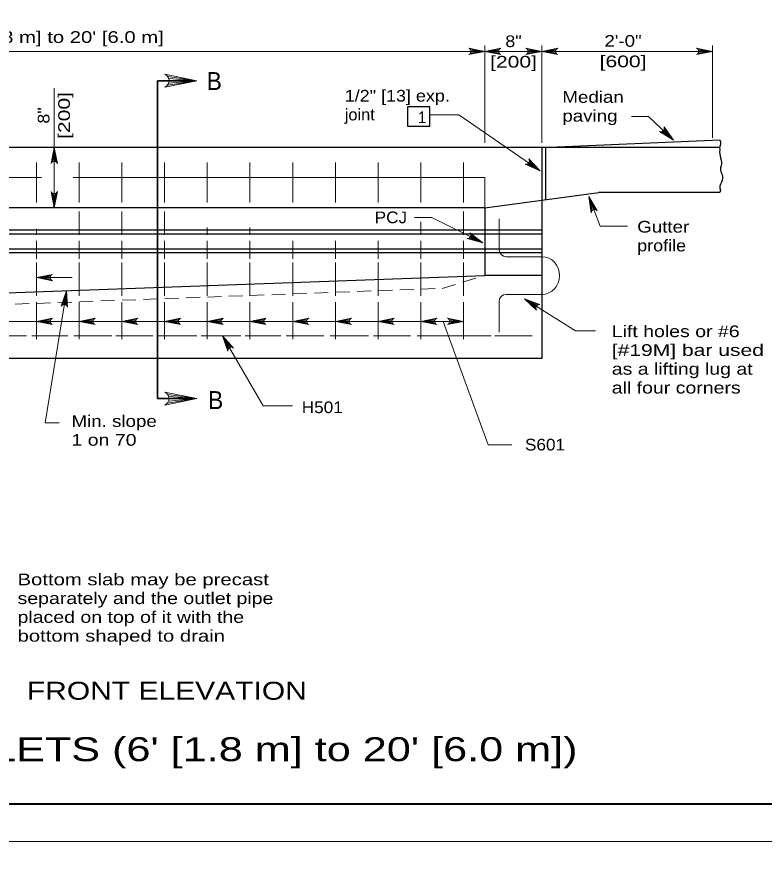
# Model space of a CAD drawing. Extents: x 339.1 to 373.1, y 1412.7 to 1456.7.
# Drawn here: x 351.05 to 361.04, y 1434.5 to 1445.77 of the extents above; entities that cross this region are included whole.
import ezdxf
from ezdxf.enums import TextEntityAlignment as Align

# ---------------------------------------------------------------- set-up
doc = ezdxf.new("R2010")
doc.units = 0
doc.header["$LTSCALE"] = 0.062
doc.linetypes.add('LONG_DASHED', pattern=[7.5, 6, -1.5])
doc.linetypes.add('MEDIUM_DASHED', pattern=[4.5, 3, -1.5])
doc.layers.add('1', color=7, linetype='Continuous', lineweight=13)

msp = doc.modelspace()

# ---------------------------------------------------------------- linework, layer by layer
at = {"layer": '1'}
for p, q in [((357.30708, 1444.08292), (357.30708, 1445.3825)), ((358.06858, 1444.08292), (358.06858, 1445.3825)), ((360.353, 1444.149), (360.353, 1445.3825)), ((357.11092, 1445.27383), (357.30708, 1445.30383)), ((357.11317, 1445.33092), (357.30708, 1445.30383)), ((357.11833, 1445.28642), (357.30708, 1445.30383)), ((357.11975, 1445.3175), (357.30708, 1445.30383)), ((357.12175, 1445.30383), (357.30708, 1445.30383)), ((357.50092, 1445.33092), (357.30708, 1445.30383)), ((357.49442, 1445.3175), (357.30708, 1445.30383)), ((357.94383, 1445.30383), (357.30708, 1445.30383)), ((357.49242, 1445.30383), (357.30708, 1445.30383)), ((357.49583, 1445.28642), (357.30708, 1445.30383)), ((357.50325, 1445.27383), (357.30708, 1445.30383)), ((358.06858, 1445.30383), (357.84117, 1445.30383)), ((357.87233, 1445.27383), (358.06858, 1445.30383)), ((357.87467, 1445.33092), (358.06858, 1445.30383)), ((357.87983, 1445.28642), (358.06858, 1445.30383)), ((357.88125, 1445.3175), (358.06858, 1445.30383)), ((357.88325, 1445.30383), (358.06858, 1445.30383)), ((358.26242, 1445.33092), (358.06858, 1445.30383)), ((358.25592, 1445.3175), (358.06858, 1445.30383)), ((359.55533, 1445.30383), (358.06858, 1445.30383)), ((358.25392, 1445.30383), (358.06858, 1445.30383)), ((358.25733, 1445.28642), (358.06858, 1445.30383)), ((358.26475, 1445.27383), (358.06858, 1445.30383)), ((360.353, 1445.30383), (359.55533, 1445.30383)), ((360.15683, 1445.27383), (360.353, 1445.30383)), ((360.15917, 1445.33092), (360.353, 1445.30383)), ((360.16425, 1445.28642), (360.353, 1445.30383)), ((360.16567, 1445.3175), (360.353, 1445.30383)), ((360.16767, 1445.30383), (360.353, 1445.30383)), ((353.06233, 1444.85225), (353.45467, 1444.91225)), ((353.06683, 1444.9665), (353.45467, 1444.91225)), ((353.07717, 1444.87742), (353.45467, 1444.91225)), ((353.08, 1444.93967), (353.45467, 1444.91225)), ((353.084, 1444.91225), (353.45467, 1444.91225)), ((359.66933, 1444.23083), (359.82817, 1444.11633)), ((359.68333, 1444.23592), (359.82817, 1444.11633)), ((359.69425, 1444.2445), (359.82817, 1444.11633)), ((359.70383, 1444.25942), (359.82817, 1444.11633)), ((359.70717, 1444.27367), (359.82817, 1444.11633)), ((351.51883, 1443.82525), (351.54883, 1444.02142)), ((351.53142, 1443.83267), (351.54883, 1444.02142)), ((351.54883, 1443.83608), (351.54883, 1444.02142)), ((351.56258, 1443.83408), (351.54883, 1444.02142)), ((351.576, 1443.8275), (351.54883, 1444.02142)), ((351.31033, 1443.81992), (351.31033, 1443.28475)), ((351.88142, 1443.81992), (351.88142, 1443.28475)), ((352.4525, 1443.81992), (352.4525, 1443.28475)), ((353.02367, 1443.81992), (353.02367, 1443.28475)), ((353.59475, 1443.81992), (353.59475, 1443.28475)), ((354.16592, 1443.81992), (354.16592, 1443.28475)), ((354.737, 1443.81992), (354.737, 1443.28475)), ((355.30817, 1443.81992), (355.30817, 1443.28475)), ((355.87925, 1443.81992), (355.87925, 1443.28475)), ((356.45042, 1443.81992), (356.45042, 1443.28475)), ((357.0215, 1443.81992), (357.0215, 1443.28475)), ((357.87158, 1443.79808), (358.046, 1443.70917)), ((357.88467, 1443.80533), (358.046, 1443.70917)), ((357.89417, 1443.81542), (358.046, 1443.70917)), ((357.90133, 1443.83167), (358.046, 1443.70917)), ((357.9025, 1443.84617), (358.046, 1443.70917)), ((351.37842, 1443.61833), (345.21833, 1443.61833)), ((357.30708, 1443.61833), (351.80117, 1443.61833)), ((357.30708, 1443.61833), (357.30708, 1443.21525)), ((351.52167, 1443.40908), (351.54883, 1443.21525)), ((351.53517, 1443.40258), (351.54883, 1443.21525)), ((351.57883, 1443.41142), (351.54883, 1443.21525)), ((351.56625, 1443.404), (351.54883, 1443.21525)), ((351.54883, 1443.40058), (351.54883, 1443.21525)), ((358.75925, 1443.18775), (358.69825, 1443.36275)), ((358.74392, 1443.17883), (358.69825, 1443.36275)), ((358.7345, 1443.16767), (358.69825, 1443.36275)), ((358.77283, 1443.19042), (358.69825, 1443.36275)), ((358.78767, 1443.18867), (358.69825, 1443.36275)), ((351.88142, 1443.16433), (351.88142, 1442.85133)), ((352.4525, 1443.16433), (352.4525, 1442.85133)), ((353.02367, 1443.16433), (353.02367, 1442.85133)), ((357.0215, 1443.16433), (357.0215, 1442.85133)), ((356.45042, 1443.02467), (356.45042, 1442.85133)), ((357.49742, 1443.06392), (357.49742, 1442.66083)), ((351.31033, 1442.93283), (351.31033, 1442.85133)), ((353.59475, 1442.95117), (353.59475, 1442.85133)), ((354.16592, 1442.95117), (354.16592, 1442.85133)), ((351.31033, 1442.77108), (351.31033, 1442.53025)), ((351.88142, 1442.77108), (351.88142, 1442.53025)), ((352.4525, 1442.77108), (352.4525, 1442.53025)), ((353.02367, 1442.77108), (353.02367, 1442.53025)), ((353.59475, 1442.77108), (353.59475, 1442.53025)), ((354.16592, 1442.77108), (354.16592, 1442.53025)), ((354.737, 1442.77108), (354.737, 1442.53025)), ((355.30817, 1442.77108), (355.30817, 1442.53025)), ((355.87925, 1442.77108), (355.87925, 1442.53025)), ((356.45042, 1442.77108), (356.45042, 1442.53025)), ((357.0215, 1442.77108), (357.0215, 1442.53025)), ((357.09442, 1442.80792), (357.28025, 1442.74625)), ((357.10625, 1442.81708), (357.28025, 1442.74625)), ((357.11417, 1442.8285), (357.28025, 1442.74625)), ((357.11775, 1442.86017), (357.28025, 1442.74625)), ((357.11875, 1442.84558), (357.28025, 1442.74625)), ((357.12208, 1442.82042), (357.28025, 1442.74625)), ((358.06858, 1442.56008), (357.59258, 1442.56008)), ((351.31033, 1442.48217), (351.31033, 1442.03675)), ((351.88142, 1442.48217), (351.88142, 1442.03675)), ((352.4525, 1442.48217), (352.4525, 1442.03675)), ((353.02367, 1442.48217), (353.02367, 1442.03675)), ((353.59475, 1442.48217), (353.59475, 1442.03675)), ((354.16592, 1442.48217), (354.16592, 1442.03675)), ((354.737, 1442.48217), (354.737, 1442.03675)), ((355.30817, 1442.48217), (355.30817, 1442.03675)), ((355.87925, 1442.48217), (355.87925, 1442.03675)), ((356.45042, 1442.48217), (356.45042, 1442.03675)), ((357.0215, 1442.48217), (357.0215, 1442.03675)), ((351.50417, 1442.30783), (351.31033, 1442.28075)), ((351.49758, 1442.29442), (351.31033, 1442.28075)), ((351.78717, 1442.28075), (351.31033, 1442.28075)), ((351.49558, 1442.28075), (351.31033, 1442.28075)), ((351.49908, 1442.26333), (351.31033, 1442.28075)), ((351.5065, 1442.25075), (351.31033, 1442.28075)), ((351.65492, 1441.91467), (351.7135, 1442.10425)), ((351.66842, 1441.92017), (351.7135, 1442.10425)), ((351.68617, 1441.921), (351.7135, 1442.10425)), ((351.69942, 1441.917), (351.7135, 1442.10425)), ((351.71175, 1441.9085), (351.7135, 1442.10425)), ((358.06858, 1442.05642), (357.59258, 1442.05642)), ((357.99617, 1441.89917), (357.83875, 1441.99708)), ((357.98983, 1441.88258), (357.83875, 1441.99708)), ((357.9895, 1441.868), (357.83875, 1441.99708)), ((358.00508, 1441.90975), (357.83875, 1441.99708)), ((358.01775, 1441.91767), (357.83875, 1441.99708)), ((357.83875, 1441.99708), (358.51858, 1441.56975)), ((351.31033, 1441.95242), (351.31033, 1441.45883)), ((351.88142, 1441.95242), (351.88142, 1441.45883)), ((352.4525, 1441.95242), (352.4525, 1441.45883)), ((353.02367, 1441.95242), (353.02367, 1441.45883)), ((353.59475, 1441.95242), (353.59475, 1441.45883)), ((354.16592, 1441.95242), (354.16592, 1441.45883)), ((354.737, 1441.95242), (354.737, 1441.45883)), ((355.30817, 1441.95242), (355.30817, 1441.45883)), ((355.87925, 1441.95242), (355.87925, 1441.45883)), ((356.45042, 1441.95242), (356.45042, 1441.45883)), ((357.0215, 1441.95242), (357.0215, 1441.45883)), ((357.49742, 1441.95567), (357.49742, 1441.5525)), ((351.50417, 1441.72317), (351.31033, 1441.696)), ((351.49758, 1441.70975), (351.31033, 1441.696)), ((351.49558, 1441.696), (351.31033, 1441.696)), ((351.49908, 1441.67858), (351.31033, 1441.696)), ((351.5065, 1441.66608), (351.31033, 1441.696)), ((352.07533, 1441.72317), (351.88142, 1441.696)), ((352.06875, 1441.70975), (351.88142, 1441.696)), ((352.06675, 1441.696), (351.88142, 1441.696)), ((352.07017, 1441.67858), (351.88142, 1441.696)), ((352.07758, 1441.66608), (351.88142, 1441.696)), ((352.64642, 1441.72317), (352.4525, 1441.696)), ((352.63983, 1441.70975), (352.4525, 1441.696)), ((352.63783, 1441.696), (352.4525, 1441.696)), ((352.64125, 1441.67858), (352.4525, 1441.696)), ((352.64875, 1441.66608), (352.4525, 1441.696)), ((353.21758, 1441.72317), (353.02367, 1441.696)), ((353.211, 1441.70975), (353.02367, 1441.696)), ((353.209, 1441.696), (353.02367, 1441.696)), ((353.21242, 1441.67858), (353.02367, 1441.696)), ((353.21983, 1441.66608), (353.02367, 1441.696)), ((353.78867, 1441.72317), (353.59475, 1441.696)), ((353.78208, 1441.70975), (353.59475, 1441.696)), ((353.78008, 1441.696), (353.59475, 1441.696)), ((353.7835, 1441.67858), (353.59475, 1441.696)), ((353.79092, 1441.66608), (353.59475, 1441.696)), ((354.35975, 1441.72317), (354.16592, 1441.696)), ((354.35325, 1441.70975), (354.16592, 1441.696)), ((354.16592, 1441.696), (354.737, 1441.696)), ((354.35125, 1441.696), (354.16592, 1441.696)), ((354.35467, 1441.67858), (354.16592, 1441.696)), ((354.36208, 1441.66608), (354.16592, 1441.696)), ((354.93092, 1441.72317), (354.737, 1441.696)), ((354.92433, 1441.70975), (354.737, 1441.696)), ((354.92233, 1441.696), (354.737, 1441.696)), ((354.92575, 1441.67858), (354.737, 1441.696)), ((354.93317, 1441.66608), (354.737, 1441.696)), ((355.502, 1441.72317), (355.30817, 1441.696)), ((355.4955, 1441.70975), (355.30817, 1441.696)), ((355.4935, 1441.696), (355.30817, 1441.696)), ((355.49692, 1441.67858), (355.30817, 1441.696)), ((355.50433, 1441.66608), (355.30817, 1441.696)), ((356.07317, 1441.72317), (355.87925, 1441.696)), ((356.06658, 1441.70975), (355.87925, 1441.696)), ((356.06458, 1441.696), (355.87925, 1441.696)), ((356.068, 1441.67858), (355.87925, 1441.696)), ((356.07542, 1441.66608), (355.87925, 1441.696)), ((356.64425, 1441.72317), (356.45042, 1441.696)), ((356.63767, 1441.70975), (356.45042, 1441.696)), ((356.63567, 1441.696), (356.45042, 1441.696)), ((356.63917, 1441.67858), (356.45042, 1441.696)), ((356.64658, 1441.66608), (356.45042, 1441.696)), ((356.82533, 1441.66608), (357.0215, 1441.696)), ((356.82758, 1441.72317), (357.0215, 1441.696)), ((356.83275, 1441.67858), (357.0215, 1441.696)), ((356.83417, 1441.70975), (357.0215, 1441.696)), ((356.83617, 1441.696), (357.0215, 1441.696)), ((358.51858, 1441.56975), (358.78617, 1441.56975)), ((351.17533, 1441.50208), (350.67025, 1441.50208)), ((351.72858, 1441.50208), (351.24758, 1441.50208)), ((352.32033, 1441.50208), (351.81033, 1441.50208)), ((352.86867, 1441.50208), (352.37325, 1441.50208)), ((353.45558, 1441.50208), (352.93608, 1441.50208)), ((354.0425, 1441.50208), (353.51342, 1441.50208)), ((353.89333, 1441.34258), (353.7985, 1441.50183)), ((353.88008, 1441.33075), (353.7985, 1441.50183)), ((353.87308, 1441.31792), (353.7985, 1441.50183)), ((353.90617, 1441.34783), (353.7985, 1441.50183)), ((353.921, 1441.34908), (353.7985, 1441.50183)), ((354.5765, 1441.50208), (354.10025, 1441.50208)), ((355.15383, 1441.50208), (354.64867, 1441.50208)), ((355.75033, 1441.50208), (355.24033, 1441.50208)), ((356.31325, 1441.50208), (355.81767, 1441.50208)), ((357.39083, 1441.50208), (356.39983, 1441.50208)), ((357.93925, 1441.50208), (357.439, 1441.50208)), ((353.06233, 1440.60367), (353.45467, 1440.66358)), ((353.06683, 1440.71783), (353.45467, 1440.66358)), ((353.07717, 1440.62875), (353.45467, 1440.66358)), ((353.08, 1440.691), (353.45467, 1440.66358)), ((353.084, 1440.66358), (353.45467, 1440.66358))]:
    msp.add_line(p, q, dxfattribs=at)
at = {"layer": '1', "lineweight": 35}
for p, q in [((352.93117, 1444.91225), (353.31067, 1444.91225)), ((352.93117, 1440.66358), (353.31067, 1440.66358))]:
    msp.add_line(p, q, dxfattribs=at)
at = {"layer": '1', "lineweight": 25}
for p, q in [((358.06858, 1444.02142), (360.44992, 1444.12217)), ((360.4375, 1444.02142), (345.16325, 1444.02142)), ((358.06858, 1444.02142), (358.06858, 1441.19975)), ((358.11617, 1444.02142), (358.11625, 1443.32233)), ((357.30708, 1443.21525), (358.83033, 1443.41675)), ((360.44992, 1443.41675), (358.83033, 1443.41675)), ((357.30708, 1443.21525), (347.12208, 1443.21525)), ((357.30708, 1443.21525), (357.30708, 1442.30825)), ((358.06858, 1442.91292), (349.66017, 1442.91292)), ((358.06858, 1442.8625), (349.62733, 1442.8625)), ((351.31033, 1442.61058), (345.21833, 1442.61058)), ((358.06858, 1442.61058), (351.29592, 1442.61058)), ((348.97067, 1442.00592), (357.30708, 1442.30825)), ((358.06858, 1442.30825), (357.30708, 1442.30825))]:
    msp.add_line(p, q, dxfattribs=at)
at = {"layer": '1', "linetype": 'LONG_DASHED'}
for points in [[(339.0605, 1434.7455), (373.0605, 1434.7455), (373.0605, 1456.7455), (339.0605, 1456.7455)], [(339.0605, 1412.7455), (373.0605, 1412.7455), (373.0605, 1434.7455), (339.0605, 1434.7455)]]:
    msp.add_lwpolyline(points, close=True, dxfattribs=at)
at = {"layer": '1', "lineweight": 25}
for points in [[(372.5605, 1435.2455), (341.0605, 1435.2455), (341.0605, 1456.2455)], [(360.44992, 1444.12217), (360.45758, 1444.09642), (360.458, 1444.07008), (360.45375, 1444.04483), (360.44658, 1444.0185), (360.44758, 1443.99075), (360.44658, 1443.95792), (360.44942, 1443.93267), (360.45183, 1443.90583), (360.45658, 1443.8795), (360.46575, 1443.85133), (360.471, 1443.8255), (360.4705, 1443.79875), (360.46575, 1443.77242), (360.45992, 1443.74567), (360.45942, 1443.71892), (360.46475, 1443.69258), (360.47717, 1443.66683), (360.48717, 1443.63908), (360.48617, 1443.61075), (360.48192, 1443.58292), (360.471, 1443.55617), (360.458, 1443.52833), (360.45092, 1443.50217), (360.44992, 1443.47683), (360.45658, 1443.45), (360.44992, 1443.41675), (360.45133, 1443.41917)], [(358.06858, 1442.661), (351.29075, 1442.661), (345.21833, 1442.661)], [(358.06858, 1441.19975), (345.50033, 1441.19975), (345.21833, 1441.19975)]]:
    msp.add_lwpolyline(points, dxfattribs=at)
at = {"layer": '1', "lineweight": 40}
msp.add_lwpolyline([(341.0605, 1456.2455), (372.5605, 1456.2455), (372.5605, 1435.2455), (341.0605, 1435.2455)], close=True, dxfattribs=at)
at = {"layer": '1'}
for points in [[(357.30708, 1445.30383), (354.73217, 1445.30383), (345.97983, 1445.30383)], [(357.09292, 1445.261), (357.30708, 1445.30383), (357.09292, 1445.34667)], [(357.52125, 1445.261), (357.30708, 1445.30383), (357.52125, 1445.34667)], [(357.85442, 1445.261), (358.06858, 1445.30383), (357.85442, 1445.34667)], [(358.28275, 1445.261), (358.06858, 1445.30383), (358.28275, 1445.34667)], [(360.13883, 1445.261), (360.353, 1445.30383), (360.13883, 1445.34667)], [(353.02633, 1444.82658), (353.45467, 1444.91225), (353.02633, 1444.99792)], [(351.54883, 1443.21525), (351.54883, 1443.4015), (351.54883, 1444.81458)], [(358.046, 1443.70917), (356.959, 1444.458), (356.5695, 1444.458)], [(359.82817, 1444.11633), (359.49667, 1444.43425), (359.26833, 1444.43425)], [(359.703, 1444.29533), (359.82817, 1444.11633), (359.64383, 1444.2335)], [(351.506, 1443.80725), (351.54883, 1444.02142), (351.59167, 1443.80725)], [(357.89508, 1443.86708), (358.046, 1443.70917), (357.846, 1443.79683)], [(351.59167, 1443.42942), (351.54883, 1443.21525), (351.506, 1443.42942)], [(358.72833, 1443.14642), (358.69825, 1443.36275), (358.80925, 1443.17467)], [(358.69825, 1443.36275), (358.84958, 1442.96658), (359.21292, 1442.96658)], [(357.28025, 1442.74625), (356.59983, 1443.08392), (356.36592, 1443.08392)], [(357.10725, 1442.87967), (357.28025, 1442.74625), (357.06925, 1442.80283)], [(351.5245, 1442.23792), (351.31033, 1442.28075), (351.5245, 1442.32358)], [(351.6395, 1441.89875), (351.7135, 1442.10425), (351.72425, 1441.88617)], [(351.70908, 1442.06767), (351.42625, 1440.33958), (351.61467, 1440.33958)], [(357.998, 1441.84758), (357.83875, 1441.99708), (358.04325, 1441.92033)], [(350.16808, 1441.696), (350.73917, 1441.696), (351.31033, 1441.696), (351.88142, 1441.696), (352.4525, 1441.696), (353.02367, 1441.696), (353.59475, 1441.696), (354.16592, 1441.696)], [(351.5245, 1441.65317), (351.31033, 1441.696), (351.5245, 1441.73883)], [(352.09558, 1441.65317), (351.88142, 1441.696), (352.09558, 1441.73883)], [(352.66667, 1441.65317), (352.4525, 1441.696), (352.66667, 1441.73883)], [(353.23783, 1441.65317), (353.02367, 1441.696), (353.23783, 1441.73883)], [(353.80892, 1441.65317), (353.59475, 1441.696), (353.80892, 1441.73883)], [(354.38008, 1441.65317), (354.16592, 1441.696), (354.38008, 1441.73883)], [(354.95117, 1441.65317), (354.737, 1441.696), (354.95117, 1441.73883)], [(357.0215, 1441.696), (356.45042, 1441.696), (355.87925, 1441.696), (355.30817, 1441.696), (354.737, 1441.696)], [(355.52233, 1441.65317), (355.30817, 1441.696), (355.52233, 1441.73883)], [(356.09342, 1441.65317), (355.87925, 1441.696), (356.09342, 1441.73883)], [(356.66458, 1441.65317), (356.45042, 1441.696), (356.66458, 1441.73883)], [(356.75125, 1441.696), (357.35058, 1440.04542), (357.6665, 1440.04542)], [(356.80733, 1441.65317), (357.0215, 1441.696), (356.80733, 1441.73883)], [(353.87125, 1441.29592), (353.7985, 1441.50183), (353.94492, 1441.33975)], [(353.7985, 1441.50183), (354.34342, 1440.56683), (354.73508, 1440.56683)], [(353.02633, 1440.57792), (353.45467, 1440.66358), (353.02633, 1440.74925)]]:
    msp.add_lwpolyline(points, dxfattribs=at)
at = {"layer": '1', "lineweight": 35}
msp.add_lwpolyline([(352.93117, 1444.91225), (352.93117, 1443.94808), (352.93117, 1440.66358)], dxfattribs=at)
at = {"layer": '1', "lineweight": 25}
msp.add_lwpolyline([(356.27083, 1444.56425), (356.27083, 1444.30267), (356.5695, 1444.30267), (356.5695, 1444.56425)], close=True, dxfattribs=at)
at = {"layer": '1', "linetype": 'MEDIUM_DASHED'}
msp.add_lwpolyline([(349.02583, 1441.85192), (356.73592, 1442.13683), (357.30708, 1442.30825)], dxfattribs=at)
at = {"layer": '1'}
for centre, radius, start, end in [((357.07559, 1445.30385), 0.04623, 292.08605, 67.91218), ((357.53852, 1445.30385), 0.04623, 112.08782, 247.91395), ((357.83708, 1445.30385), 0.04623, 292.08605, 67.91218), ((358.30001, 1445.30385), 0.04623, 112.08782, 247.91395), ((360.12156, 1445.30385), 0.04623, 292.08605, 67.91218), ((352.99173, 1444.91235), 0.09245, 292.08605, 67.91218), ((359.66089, 1444.27634), 0.04623, 248.35541, 24.18154), ((351.54888, 1443.78996), 0.04623, 22.08782, 157.91395), ((357.85635, 1443.84184), 0.04623, 257.09017, 32.9163), ((351.54879, 1443.44669), 0.04623, 202.08782, 337.91395), ((358.77451, 1443.14424), 0.04623, 41.32463, 177.15076), ((357.07276, 1442.84889), 0.04623, 265.74352, 41.56965), ((351.54176, 1442.28078), 0.04623, 112.08782, 247.91395), ((351.67939, 1441.87534), 0.04623, 13.60269, 149.42881), ((358.03534, 1441.87485), 0.04623, 80.20777, 216.0339), ((351.54176, 1441.69609), 0.04623, 112.08782, 247.91395), ((352.11288, 1441.69609), 0.04623, 112.08782, 247.91395), ((352.684, 1441.69609), 0.04623, 112.08782, 247.91395), ((353.25512, 1441.69609), 0.04623, 112.08782, 247.91395), ((353.82624, 1441.69609), 0.04623, 112.08782, 247.91395), ((354.39736, 1441.69609), 0.04623, 112.08782, 247.91395), ((354.96848, 1441.69609), 0.04623, 112.08782, 247.91395), ((355.5396, 1441.69609), 0.04623, 112.08782, 247.91395), ((356.11072, 1441.69609), 0.04623, 112.08782, 247.91395), ((356.68184, 1441.69609), 0.04623, 112.08782, 247.91395), ((356.79003, 1441.69609), 0.04623, 292.08605, 67.91218), ((353.91697, 1441.30296), 0.04623, 52.8601, 188.68622), ((352.99173, 1440.66369), 0.09245, 292.08605, 67.91218)]:
    msp.add_arc(centre, radius, start, end, dxfattribs=at)
for centre, major_axis, start_param, end_param in [((357.59262, 1442.66086), (0, 0.10078), 1.57079628, 3.14159256), ((358.06855, 1442.30825), (0, 0.25194), 3.14159261, 6.28318526), ((357.59262, 1441.95564), (0, 0.10078), 6.28318526, 7.85398154)]:
    msp.add_ellipse(centre, major_axis=major_axis, ratio=0.944544, start_param=start_param, end_param=end_param, dxfattribs=at)

# ---------------------------------------------------------------- texts
for s, height, width, p in [("Variable 6' [1.8 m] to 20' [6.0 m]", 0.156, 1.3, (349.20175, 1445.41742)), ('B', 0.24, 0.95, (353.58642, 1444.7875)), ('1/2" [13] exp.', 0.156, 1.15, (355.43333, 1444.63317)), ('Median', 0.156, 1.2, (358.3435, 1444.61658)), ('joint', 0.156, 1.05, (355.43333, 1444.382)), ('paving', 0.156, 1.2, (358.3435, 1444.36542)), ('PCJ', 0.156, 1.1, (355.83358, 1443.00783)), ('Gutter', 0.156, 1.2, (359.34442, 1442.88242)), ('profile', 0.156, 1.15, (359.34442, 1442.63125)), ('Lift holes or #6', 0.156, 1.25, (359.00383, 1441.48508)), ('[#19M] bar used', 0.156, 1.35, (359.00383, 1441.23392)), ('as a lifting lug at', 0.156, 1.25, (359.00383, 1440.98275)), ('all four corners', 0.156, 1.25, (359.00383, 1440.73158)), ('B', 0.24, 0.95, (353.60525, 1440.52325)), ('H501', 0.156, 1.1, (354.85842, 1440.46983)), ('Min. slope', 0.156, 1.2, (351.77875, 1440.285)), ('1 on 70', 0.156, 1.25, (351.77875, 1440.03383)), ('S601', 0.156, 1.1, (357.84342, 1439.97058)), ('Bottom slab may be precast', 0.156, 1.3, (351.0575, 1438.16867)), ('separately and the outlet pipe', 0.156, 1.25, (351.0575, 1437.9175)), ('placed on top of it with the', 0.156, 1.25, (351.0575, 1437.66633)), ('bottom shaped to drain', 0.156, 1.3, (351.0575, 1437.41517)), ('FRONT ELEVATION', 0.24, 1.25, (351.18175, 1436.63883)), ("MEDIAN INLETS (6' [1.8 m] to 20' [6.0 m])", 0.32, 1.35, (347.7315, 1435.81808))]:
    msp.add_text(s, height=height, dxfattribs=dict(at, width=width)).set_placement(p)
for s, width, p in [('8"', 1.15, (357.69004, 1445.36158)), ('2\'-0"', 1.2, (359.15508, 1445.36608)), ('[200]', 1.35, (357.69012, 1445.08758)), ('[600]', 1.35, (359.15525, 1445.09208))]:
    msp.add_text(s, height=0.156, dxfattribs=dict(at, width=width)).set_placement(p, align=Align.CENTER)
for s, width, p in [('[200]', 1.35, (351.75775, 1444.44742)), ('8"', 1.15, (351.48375, 1444.44742))]:
    msp.add_text(s, height=0.156, rotation=90, dxfattribs=dict(at, width=width)).set_placement(p, align=Align.CENTER)
msp.add_text('1', height=0.156, dxfattribs=at).set_placement((356.40967, 1444.34517))

doc.saveas('drawing.dxf')
